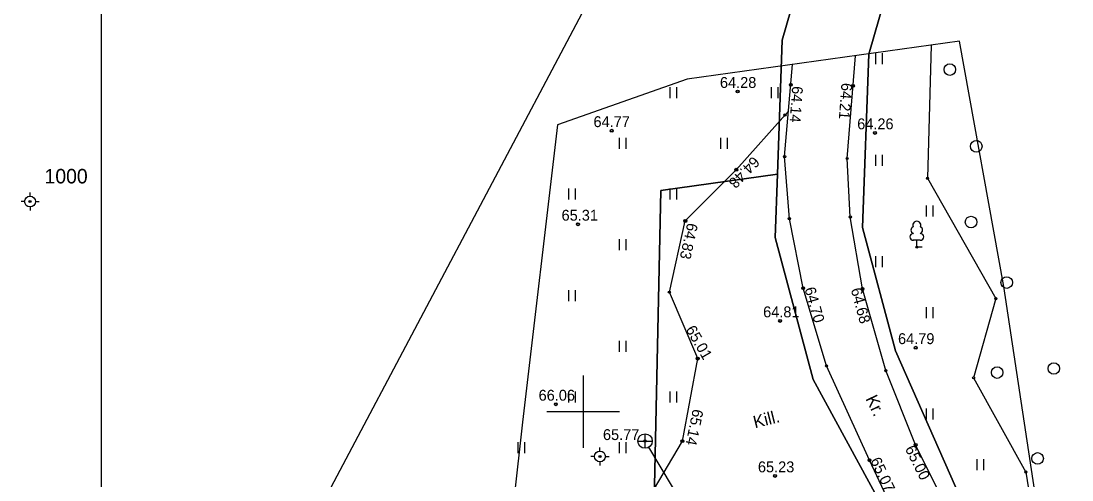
# Model space of a CAD drawing. Extents: x 598011 to 598230, y 6478330 to 6478537.
# Drawn here: x 598011.2 to 598083.7, y 6478445.3 to 6478476.9 of the extents above; entities that cross this region are included whole.
import ezdxf

# ---------------------------------------------------------------- set-up
doc = ezdxf.new("R2010")
doc.units = 0
for name, color, linetype in [('ALUSVORK', 7, 'Continuous'), ('HALJASTUS', 7, 'Continuous'), ('KKAEV', 7, 'Continuous'), ('KORGUS-EH2000', 7, 'Continuous'), ('KTRASS', 7, 'Continuous'), ('MOOTMPUNKT', 7, 'Continuous'), ('MOOTPIIR', 7, 'Continuous'), ('PIIR', 7, 'Continuous'), ('PUU', 7, 'Continuous'), ('TEE', 7, 'Continuous'), ('VORK', 7, 'Continuous'), ('VORMISTUS', 7, 'Continuous')]:
    doc.layers.add(name, color=color, linetype=linetype)

msp = doc.modelspace()

# ---------------------------------------------------------------- linework, layer by layer
at = {"layer": 'ALUSVORK'}
for p, q in [((598011.828, 6478464.864), (598011.828, 6478465.114)), ((598011.453, 6478464.489), (598011.203, 6478464.489)), ((598011.828, 6478464.114), (598011.828, 6478463.864)), ((598012.203, 6478464.489), (598012.453, 6478464.489)), ((598051.162, 6478447.281), (598051.162, 6478447.531)), ((598050.787, 6478446.906), (598050.537, 6478446.906)), ((598051.162, 6478446.531), (598051.162, 6478446.281)), ((598051.537, 6478446.906), (598051.787, 6478446.906))]:
    msp.add_line(p, q, dxfattribs=at)
for centre, radius in [((598011.828, 6478464.489), 0.375), ((598011.828, 6478464.489), 0.022), ((598051.162, 6478446.906), 0.375), ((598051.162, 6478446.906), 0.022)]:
    msp.add_circle(centre, radius, dxfattribs=at)
at = {"layer": 'HALJASTUS'}
for p, q in [((598070.181, 6478474.714), (598070.181, 6478473.953)), ((598070.636, 6478474.714), (598070.636, 6478473.953)), ((598055.987, 6478472.385), (598055.987, 6478471.624)), ((598056.442, 6478472.385), (598056.442, 6478471.624)), ((598062.987, 6478472.385), (598062.987, 6478471.624)), ((598063.442, 6478472.385), (598063.442, 6478471.624)), ((598052.487, 6478468.885), (598052.487, 6478468.124)), ((598052.942, 6478468.885), (598052.942, 6478468.124)), ((598059.487, 6478468.885), (598059.487, 6478468.124)), ((598059.942, 6478468.885), (598059.942, 6478468.124)), ((598070.181, 6478467.714), (598070.181, 6478466.953)), ((598070.636, 6478467.714), (598070.636, 6478466.953)), ((598048.987, 6478465.385), (598048.987, 6478464.624)), ((598049.442, 6478465.385), (598049.442, 6478464.624)), ((598055.987, 6478465.385), (598055.987, 6478464.624)), ((598056.442, 6478465.385), (598056.442, 6478464.624)), ((598073.681, 6478464.214), (598073.681, 6478463.453)), ((598074.136, 6478464.214), (598074.136, 6478463.453)), ((598052.487, 6478461.885), (598052.487, 6478461.124)), ((598052.942, 6478461.885), (598052.942, 6478461.124)), ((598070.181, 6478460.714), (598070.181, 6478459.953)), ((598070.636, 6478460.714), (598070.636, 6478459.953)), ((598048.987, 6478458.385), (598048.987, 6478457.624)), ((598049.442, 6478458.385), (598049.442, 6478457.624)), ((598073.681, 6478457.214), (598073.681, 6478456.453)), ((598074.136, 6478457.214), (598074.136, 6478456.453)), ((598052.487, 6478454.885), (598052.487, 6478454.124)), ((598052.942, 6478454.885), (598052.942, 6478454.124)), ((598048.987, 6478451.385), (598048.987, 6478450.624)), ((598049.442, 6478451.385), (598049.442, 6478450.624)), ((598055.987, 6478451.385), (598055.987, 6478450.624)), ((598056.442, 6478451.385), (598056.442, 6478450.624)), ((598073.681, 6478450.214), (598073.681, 6478449.453)), ((598074.136, 6478450.214), (598074.136, 6478449.453)), ((598045.487, 6478447.885), (598045.487, 6478447.124)), ((598045.942, 6478447.885), (598045.942, 6478447.124)), ((598052.487, 6478447.885), (598052.487, 6478447.124)), ((598052.942, 6478447.885), (598052.942, 6478447.124)), ((598077.181, 6478446.714), (598077.181, 6478445.953)), ((598077.636, 6478446.714), (598077.636, 6478445.953))]:
    msp.add_line(p, q, dxfattribs=at)
msp.add_lwpolyline([(598074.027, 6478475.285), (598073.77, 6478466.095), (598078.481, 6478457.792), (598076.946, 6478452.332), (598080.553, 6478445.829), (598081.491, 6478439.919), (598087.787, 6478418.044), (598088.752, 6478412.268)], dxfattribs=at)
for centre in [(598075.309, 6478473.591), (598077.133, 6478468.297), (598076.769, 6478463.075), (598079.232, 6478458.901), (598078.576, 6478452.694), (598082.484, 6478452.975), (598081.366, 6478446.77)]:
    msp.add_circle(centre, 0.4, dxfattribs=at)
at = {"layer": 'KKAEV'}
for p, q in [((598053.772, 6478447.969), (598054.772, 6478447.969)), ((598054.272, 6478447.469), (598054.272, 6478448.469))]:
    msp.add_line(p, q, dxfattribs=at)
msp.add_circle((598054.272, 6478447.969), 0.5, dxfattribs=at)
at = {"layer": 'KORGUS-EH2000'}
for centre in [(598064.336, 6478472.547), (598060.662, 6478472.076), (598068.621, 6478472.464), (598051.971, 6478469.372), (598070.138, 6478469.222), (598060.567, 6478466.685), (598057.052, 6478463.147), (598049.643, 6478462.919), (598065.186, 6478458.512), (598069.283, 6478458.458), (598063.593, 6478456.253), (598072.955, 6478454.406), (598057.909, 6478453.658), (598048.113, 6478450.504), (598056.847, 6478447.971), (598072.945, 6478447.7), (598069.764, 6478446.643), (598063.246, 6478445.564)]:
    msp.add_circle(centre, 0.1, dxfattribs=at)
at = {"layer": 'KTRASS'}
msp.add_lwpolyline([(598062.121, 6478434.837), (598054.532, 6478447.542)], dxfattribs=at)
at = {"layer": 'MOOTMPUNKT'}
for centre in [(598064.336, 6478472.547), (598060.662, 6478472.076), (598068.621, 6478472.464), (598063.936, 6478470.459), (598051.971, 6478469.372), (598070.138, 6478469.222), (598063.905, 6478467.586), (598068.218, 6478467.462), (598060.567, 6478466.685), (598073.77, 6478466.095), (598011.828, 6478464.489), (598057.052, 6478463.147), (598064.231, 6478463.307), (598068.438, 6478463.424), (598049.643, 6478462.919), (598073.028, 6478461.341), (598055.952, 6478458.236), (598065.186, 6478458.512), (598069.283, 6478458.458), (598078.481, 6478457.792), (598063.593, 6478456.253), (598072.955, 6478454.406), (598057.909, 6478453.658), (598066.794, 6478453.152), (598070.89, 6478452.828), (598076.946, 6478452.332), (598048.113, 6478450.504), (598054.272, 6478447.969), (598056.847, 6478447.971), (598072.945, 6478447.7), (598051.162, 6478446.906), (598069.764, 6478446.643), (598080.553, 6478445.829), (598063.246, 6478445.564)]:
    msp.add_circle(centre, 0.075, dxfattribs=at)
at = {"layer": 'MOOTPIIR'}
msp.add_lwpolyline([(598075.982, 6478475.56), (598057.177, 6478472.92), (598048.24, 6478469.789), (598045.814, 6478449.279), (598044.645, 6478438.772), (598046.991, 6478414.508), (598054.253, 6478402.767), (598060.844, 6478399.077), (598071.972, 6478405.5), (598083.023, 6478407.009), (598085.912, 6478407.009), (598087.125, 6478415.828), (598086.295, 6478424.582), (598081.666, 6478441.29), (598079.041, 6478458.618)], close=True, dxfattribs=at)
at = {"layer": 'PIIR'}
for points in [[(598011.79, 6478405.5), (598081.48, 6478537.03), (598087.81, 6478533.61), (598081.1, 6478522.41), (598073.68, 6478503.38), (598068.04, 6478490.52), (598063.74, 6478475.61), (598063.42, 6478466.37), (598055.37, 6478465.26), (598054.72, 6478435.22), (598057.87, 6478421.2), (598067.5, 6478424), (598075.6, 6478425.87), (598075.95, 6478425.95), (598080.86, 6478427.08), (598083.16, 6478418.05), (598077.61, 6478417.15), (598069.31, 6478414.97), (598050.5, 6478410.56), (598053.52, 6478386.1), (598055.7, 6478377.93), (598019.25, 6478379.83)], [(598081.1, 6478522.41), (598087.81, 6478533.61), (598092.94, 6478530.49), (598086.45, 6478519.6), (598079.22, 6478501.09), (598073.69, 6478488.47), (598069.71, 6478474.66), (598069.29, 6478462.69), (598071.55, 6478454.2), (598077.2, 6478441.43), (598080.86, 6478427.08), (598075.95, 6478425.95), (598072.84, 6478439.42), (598065.87, 6478452.21), (598063.26, 6478462.01), (598063.42, 6478466.37), (598063.74, 6478475.61), (598068.04, 6478490.52), (598073.68, 6478503.38)], [(598093.38, 6478381.19), (598086.49, 6478418.82), (598083.16, 6478418.05), (598080.86, 6478427.08), (598077.2, 6478441.43), (598071.55, 6478454.2), (598069.29, 6478462.69), (598069.71, 6478474.66), (598073.69, 6478488.47), (598079.22, 6478501.09), (598086.45, 6478519.6), (598092.94, 6478530.49), (598127.2, 6478509.56), (598154.27, 6478492.13), (598192.62, 6478466.21), (598223.81, 6478441.55), (598229.65, 6478435.94), (598191.25, 6478412.44), (598173.37, 6478396.18), (598161.58, 6478385.58), (598151.68, 6478381.11), (598144.54, 6478375.38)], [(598054.72, 6478435.22), (598055.37, 6478465.26), (598063.42, 6478466.37), (598063.26, 6478462.01), (598065.87, 6478452.21), (598072.84, 6478439.42), (598075.95, 6478425.95), (598075.6, 6478425.87), (598067.5, 6478424), (598057.87, 6478421.2)]]:
    msp.add_lwpolyline(points, close=True, dxfattribs=at)
at = {"layer": 'PUU'}
for p, q in [((598073.268, 6478461.816), (598072.788, 6478461.816)), ((598073.028, 6478461.341), (598073.028, 6478461.816)), ((598073.408, 6478461.341), (598073.028, 6478461.341))]:
    msp.add_line(p, q, dxfattribs=at)
for centre, radius, start, end in [((598072.858, 6478462.514), 0.233, 109.02174, 253.14154), ((598073.028, 6478462.861), 0.277, 332.5799, 207.4201), ((598073.198, 6478462.514), 0.233, 286.85082, 70.98591), ((598072.791, 6478462.053), 0.238, 90.0016, 269.3953), ((598073.265, 6478462.053), 0.238, 270.6047, 89.9984)]:
    msp.add_arc(centre, radius, start, end, dxfattribs=at)
at = {"layer": 'TEE'}
for points in [[(598083.023, 6478407.009), (598082.86, 6478413.124), (598081.386, 6478422.423), (598079.441, 6478431.381), (598076.505, 6478440.548), (598072.945, 6478447.7), (598070.89, 6478452.828), (598069.283, 6478458.458), (598068.438, 6478463.424), (598068.218, 6478467.462), (598068.789, 6478474.55)], [(598070.678, 6478410.454), (598070.622, 6478409.694), (598070.958, 6478409.123), (598071.48, 6478408.732), (598072.088, 6478408.424), (598073.872, 6478408.153), (598075.289, 6478408.445), (598076.915, 6478408.925), (598078.103, 6478409.593), (598078.785, 6478410.211), (598079.255, 6478410.806), (598079.586, 6478412.147), (598077.84, 6478421.699), (598076.015, 6478430.626), (598075.01, 6478434.257), (598072.988, 6478439.778), (598069.764, 6478446.643), (598066.794, 6478453.152), (598065.186, 6478458.512), (598064.231, 6478463.307), (598063.905, 6478467.586), (598064.457, 6478473.942)], [(598071.972, 6478405.5), (598068.524, 6478406.906), (598065.625, 6478408.796), (598062.762, 6478411.945), (598056.731, 6478419.641), (598055.627, 6478427.092), (598054.548, 6478434.457), (598052.912, 6478441.326), (598056.847, 6478447.971), (598057.909, 6478453.658), (598055.952, 6478458.236), (598057.052, 6478463.147), (598060.567, 6478466.685), (598064.178, 6478470.73)]]:
    msp.add_lwpolyline(points, dxfattribs=at)
at = {"layer": 'VORK'}
for p, q in [((598050, 6478452.5), (598050, 6478447.5)), ((598047.5, 6478450), (598052.5, 6478450))]:
    msp.add_line(p, q, dxfattribs=at)
at = {"layer": 'VORMISTUS'}
msp.add_lwpolyline([(598109.249, 6478361.639), (598016.749, 6478361.639), (598016.749, 6478504.139), (598109.249, 6478504.139), (598109.249, 6478361.639)], dxfattribs=at)

# ---------------------------------------------------------------- texts
at = {"layer": 'ALUSVORK'}
msp.add_text('1000', height=1, dxfattribs=at).set_placement((598012.828, 6478465.739))
at = {"layer": 'KORGUS-EH2000'}
for s, p in [('64.28', (598059.441, 6478472.326)), ('64.77', (598050.715, 6478469.622)), ('64.26', (598068.913, 6478469.472)), ('65.31', (598048.511, 6478463.169)), ('64.81', (598062.423, 6478456.503)), ('64.79', (598071.734, 6478454.656)), ('66.06', (598046.926, 6478450.754)), ('65.77', (598051.368, 6478448.038)), ('65.23', (598062.063, 6478445.814))]:
    msp.add_text(s, height=0.75, dxfattribs=at).set_placement(p)
for s, rotation, p in [('64.21', 265.81245, (598067.83, 6478472.689)), ('64.14', 266.05639, (598064.426, 6478472.468)), ('64.48', 226.13057, (598061.717, 6478467.66)), ('64.83', 257.70733, (598057.198, 6478463.054)), ('64.70', 286.02894, (598065.271, 6478458.471)), ('64.68', 285.11777, (598068.465, 6478458.427)), ('65.01', 300.18047, (598057.048, 6478455.672)), ('65.14', 258.3123, (598057.576, 6478450.216)), ('65.00', 296.41243, (598072.193, 6478447.442)), ('65.07', 295.43055, (598069.805, 6478446.634))]:
    msp.add_text(s, height=0.75, rotation=rotation, dxfattribs=at).set_placement(p)
at = {"layer": 'TEE'}
for s, rotation, p in [('Kr.', 295.86116, (598069.471, 6478450.892)), ('Kill.', 14.05477, (598061.858, 6478448.847))]:
    msp.add_text(s, height=0.85, rotation=rotation, dxfattribs=at).set_placement(p)

doc.saveas('drawing.dxf')
